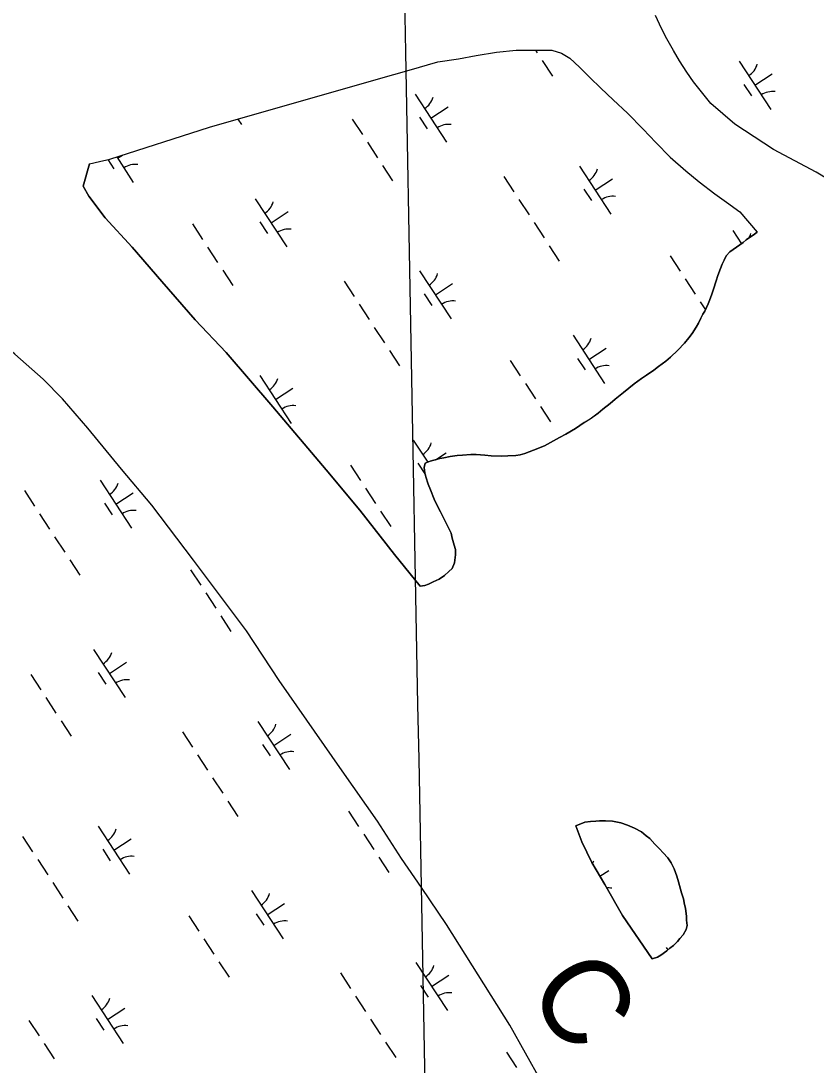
# Model space of a CAD drawing. Extents: x 3945642 to 3966284, y 206476 to 228921.
# Drawn here: x 3961973 to 3962666, y 215429 to 216338 of the extents above; entities that cross this region are included whole.
import ezdxf

# ---------------------------------------------------------------- set-up
doc = ezdxf.new("R2010")
doc.units = 0
for name, color, linetype in [('V-GRID-MAJR', 7, 'Continuous'), ('V-RIVR-IDEN', 7, 'Continuous'), ('V-TOPO-SHOR', 7, 'Continuous'), ('V-WETL-SWMP', 7, 'Continuous')]:
    doc.layers.add(name, color=color, linetype=linetype)

msp = doc.modelspace()

# ---------------------------------------------------------------- linework, layer by layer
at = {"layer": 'V-GRID-MAJR'}
msp.add_spline([(3962398.82, 211465.27), (3962380.88, 212428.56), (3962268.05, 218488.48), (3962267.27, 218530.32)], degree=3, dxfattribs=at)
at = {"layer": 'V-TOPO-SHOR'}
for points in [[(3962665.82, 216206.13), (3962628.66, 216225.93), (3962595.09, 216247.97), (3962574.2, 216266.08), (3962558.97, 216285), (3962553.28, 216293.31), (3962546.93, 216303.24), (3962541.71, 216312.12), (3962535.84, 216322.41), (3962531.09, 216331.29), (3962525.89, 216342.71)], [(3962033.13, 216213.59), (3962041.94, 216215.43), (3962050.86, 216217.6), (3962137.79, 216245.49), (3962284.94, 216287.61), (3962311.6, 216294.91), (3962336.59, 216302.33), (3962354.54, 216304.9), (3962369.81, 216307.71), (3962387.65, 216310.61), (3962404.81, 216312.51), (3962435.77, 216312.44), (3962444.22, 216309.72), (3962451.33, 216305.44), (3962459.85, 216297.59), (3962468.82, 216288.63), (3962478.34, 216279.33), (3962488.98, 216269.13), (3962501.71, 216257.47), (3962515.22, 216243.58), (3962526.18, 216232.16), (3962538.69, 216219.39), (3962552.43, 216207.28), (3962563.95, 216197.74), (3962577.59, 216187.3), (3962587.79, 216180.23), (3962599.44, 216171.8), (3962614.54, 216154.01)], [(3962033.13, 216213.59), (3962027.54, 216193.99), (3962032.54, 216185.36), (3962046.9, 216166.42), (3962070.25, 216140.88), (3962096.16, 216110.95), (3962125.32, 216077.58), (3962152.2, 216049.15), (3962192.76, 216002.06), (3962239.29, 215947.29), (3962268.58, 215912.15), (3962298.81, 215873.32), (3962321.04, 215845.87)], [(3962596.53, 215120.17), (3962538.23, 215226.12), (3962486.2, 215320.53), (3962426.39, 215415), (3962399.23, 215463.78), (3962344.02, 215551.39), (3962322.36, 215583.48), (3962304.75, 215608.71), (3962284.05, 215641.21), (3962253.16, 215685.1), (3962198.45, 215763.69), (3962169.75, 215807.02), (3962123.81, 215868.62), (3962087.49, 215916.5), (3962061.18, 215947.8), (3962031.61, 215983.49), (3962009.78, 216008.89), (3961992.8, 216026.2), (3961968.21, 216047.92), (3961939.27, 216072.68), (3961907.85, 216096.08), (3961870.85, 216121.16), (3961828.9, 216140.94), (3961793.45, 216157.39)], [(3962321.04, 215845.87), (3962325.15, 215846.53), (3962328.34, 215847.65), (3962332.45, 215849.67), (3962337.7, 215851.92), (3962342.27, 215855.08), (3962346.17, 215858.7), (3962348.91, 215861.41), (3962350.99, 215866.18), (3962351.94, 215873.23), (3962351.75, 215877.79), (3962350.63, 215881.44), (3962349.07, 215887.6), (3962347.96, 215891.93), (3962344.81, 215898.55), (3962342.33, 215903.58), (3962338.73, 215910.65), (3962336.03, 215916.13), (3962333.33, 215921.62), (3962329.96, 215929.61), (3962328.17, 215934.62), (3962326.16, 215941.01), (3962325.27, 215944.66), (3962324.62, 215949.22), (3962325.32, 215953.08), (3962329.66, 215954.65), (3962333.08, 215955.54), (3962338.32, 215956.88), (3962341.74, 215957.54), (3962347.21, 215958.65), (3962353.37, 215959.52), (3962357.92, 215959.95), (3962365.21, 215960.36), (3962369.77, 215960.56), (3962377.5, 215959.83), (3962382.96, 215959.34), (3962391.85, 215959.06), (3962397.31, 215959.26), (3962404.37, 215959.67), (3962408.25, 215960.33), (3962412.12, 215961.45), (3962419.88, 215964.13), (3962429.24, 215968.18), (3962434.49, 215970.88), (3962442.48, 215975.16), (3962447.97, 215978.31), (3962456.2, 215983.27), (3962463.97, 215988.46), (3962469, 215991.4), (3962476.08, 215996.59), (3962480.2, 215999.98), (3962486.38, 216004.95), (3962490.95, 216008.57), (3962498.05, 216014.45), (3962502.85, 216018.29), (3962507.43, 216022.13), (3962513.83, 216026.65), (3962518.17, 216029.58), (3962524.58, 216033.87), (3962528.69, 216037.03), (3962535.1, 216041.78), (3962538.98, 216045.17), (3962545.4, 216051.28), (3962551.13, 216057.39), (3962555.02, 216062.15), (3962557.78, 216065.78), (3962561.46, 216071.45), (3962563.3, 216074.85), (3962565.37, 216079.17), (3962567.21, 216082.57), (3962568.82, 216085.29), (3962571.82, 216091.65), (3962572.98, 216094.6), (3962575.06, 216100.06), (3962576.45, 216104.38), (3962578.77, 216111.65), (3962580.16, 216116.19), (3962582.48, 216122.33), (3962584.09, 216126.19), (3962585.71, 216129.59), (3962587.55, 216133.45), (3962590.76, 216136.85), (3962602.19, 216144.98), (3962604.94, 216147.24), (3962607.91, 216149.27), (3962610.88, 216151.53), (3962614.54, 216154.01)], [(3962523.04, 215521.51), (3962527.84, 215523.07), (3962530.58, 215524.65), (3962535.83, 215528.49), (3962538.35, 215530.75), (3962541.56, 215533.01), (3962544.99, 215536.63), (3962547.06, 215539.12), (3962550.04, 215542.52), (3962552.57, 215547.06), (3962553.5, 215550.47), (3962553.07, 215555.03), (3962552.86, 215558.44), (3962552.22, 215565.73), (3962551.33, 215568.7), (3962550.22, 215573.71), (3962548.66, 215578.96), (3962546.87, 215585.34), (3962545.98, 215588.54), (3962544.42, 215593.33), (3962542.18, 215599.94), (3962539.48, 215604.97), (3962536.77, 215609.31), (3962532.7, 215613.89), (3962529.53, 215617.33), (3962525.46, 215621.45), (3962520.93, 215626.26), (3962517.99, 215628.55), (3962513.68, 215631.99), (3962507.55, 215635.21), (3962501.65, 215637.98), (3962495.74, 215639.84), (3962488.46, 215641.48), (3962482.32, 215641.51), (3962477.31, 215641.54), (3962473.89, 215641.33), (3962469.33, 215640.91), (3962464.32, 215640.48), (3962456.53, 215637.32)], [(3962456.53, 215637.32), (3962461.91, 215623.22), (3962470.54, 215605.27), (3962481.77, 215586.08), (3962497.18, 215559.36), (3962523.04, 215521.51)]]:
    msp.add_lwpolyline(points, dxfattribs=at)
at = {"layer": 'V-WETL-SWMP'}
for p, q in [((3962531.1, 216331.29), (3962525.89, 216342.71)), ((3962535.84, 216322.41), (3962531.1, 216331.29)), ((3962541.71, 216312.12), (3962535.84, 216322.41)), ((3962421.43, 216312.47), (3962423.04, 216310)), ((3962546.93, 216303.24), (3962541.71, 216312.12)), ((3962427.43, 216303.31), (3962436.2, 216289.93)), ((3962553.28, 216293.31), (3962546.93, 216303.24)), ((3962598.89, 216302.76), (3962626.29, 216260.93)), ((3962558.97, 216285), (3962553.28, 216293.31)), ((3962612.59, 216281.85), (3962627.65, 216291.71)), ((3962574.2, 216266.08), (3962558.97, 216285)), ((3962602.85, 216282.64), (3962609.42, 216272.6)), ((3962316.68, 216274.15), (3962344.08, 216232.32)), ((3962595.09, 216247.97), (3962574.2, 216266.08)), ((3962330.38, 216253.24), (3962345.44, 216263.1)), ((3962162.33, 216252.51), (3962165.52, 216247.64)), ((3962261.99, 216252.31), (3962270.75, 216238.93)), ((3962320.64, 216254.03), (3962327.21, 216243.99)), ((3962628.66, 216225.93), (3962595.09, 216247.97)), ((3962275.14, 216232.23), (3962283.91, 216218.85)), ((3962056.86, 216219.53), (3962071.35, 216197.4)), ((3962057.65, 216218.31), (3962062.06, 216221.19)), ((3962665.82, 216206.13), (3962628.66, 216225.93)), ((3962049.16, 216217.19), (3962054.49, 216209.06)), ((3962288.29, 216212.16), (3962297.06, 216198.78)), ((3962459.75, 216211.61), (3962487.15, 216169.78)), ((3962393.96, 216202.48), (3962402.73, 216189.1)), ((3962473.45, 216190.69), (3962488.51, 216200.56)), ((3962715.54, 216176.43), (3962665.82, 216206.13)), ((3962463.71, 216191.49), (3962470.29, 216181.45)), ((3962177.54, 216183), (3962204.94, 216141.17)), ((3962407.11, 216182.41), (3962415.88, 216169.02)), ((3962191.24, 216162.08), (3962206.3, 216171.95)), ((3962122.85, 216161.16), (3962131.62, 216147.78)), ((3962181.5, 216162.88), (3962188.07, 216152.84)), ((3962420.26, 216162.33), (3962429.03, 216148.95)), ((3962593.34, 216155.38), (3962600.8, 216143.99)), ((3962136, 216141.08), (3962144.77, 216127.7)), ((3962433.41, 216142.26), (3962442.18, 216128.87)), ((3962538.65, 216133.54), (3962547.41, 216120.16)), ((3962149.15, 216121.01), (3962157.92, 216107.62)), ((3962320.61, 216120.45), (3962348.01, 216078.63)), ((3962254.82, 216111.33), (3962263.59, 216097.95)), ((3962334.31, 216099.54), (3962349.37, 216109.41)), ((3962551.8, 216113.47), (3962560.57, 216100.08)), ((3962324.57, 216100.33), (3962331.15, 216090.3)), ((3962267.97, 216091.25), (3962276.74, 216077.87)), ((3962564.95, 216093.39), (3962569.42, 216086.56)), ((3962281.12, 216071.18), (3962289.89, 216057.8)), ((3962454.2, 216064.23), (3962481.6, 216022.4)), ((3961992.8, 216026.2), (3961968.21, 216047.92)), ((3962294.28, 216051.1), (3962303.04, 216037.72)), ((3962467.9, 216043.32), (3962482.96, 216053.18)), ((3962399.51, 216042.39), (3962408.27, 216029.01)), ((3962458.16, 216044.11), (3962464.73, 216034.07)), ((3962181.47, 216029.3), (3962208.87, 215987.48)), ((3962009.77, 216008.88), (3961992.8, 216026.2)), ((3962412.66, 216022.32), (3962421.43, 216008.93)), ((3962195.17, 216008.39), (3962210.23, 216018.26)), ((3962031.61, 215983.49), (3962009.77, 216008.88)), ((3962425.81, 216002.24), (3962434.58, 215988.86)), ((3962061.18, 215947.8), (3962031.61, 215983.49)), ((3962315.06, 215973.08), (3962327.62, 215953.91)), ((3962334.45, 215955.89), (3962343.82, 215962.03)), ((3962087.49, 215916.5), (3962061.18, 215947.8)), ((3962260.37, 215951.24), (3962269.14, 215937.86)), ((3962319.02, 215952.96), (3962325.59, 215942.92)), ((3962042.34, 215938.15), (3962069.74, 215896.33)), ((3961976.54, 215929.03), (3961985.31, 215915.64)), ((3962273.52, 215931.16), (3962282.29, 215917.78)), ((3962056.04, 215917.24), (3962071.09, 215927.1)), ((3962046.29, 215918.03), (3962052.87, 215907.99)), ((3962123.81, 215868.62), (3962087.49, 215916.5)), ((3962286.67, 215911.09), (3962295.44, 215897.7)), ((3961989.69, 215908.95), (3961998.46, 215895.57)), ((3962002.85, 215888.88), (3962011.61, 215875.49)), ((3962016, 215868.8), (3962024.77, 215855.42)), ((3962169.75, 215807.02), (3962123.81, 215868.62)), ((3962121.23, 215860.09), (3962130, 215846.7)), ((3962134.38, 215840.01), (3962143.15, 215826.63)), ((3962147.53, 215819.94), (3962156.3, 215806.55)), ((3962198.45, 215763.69), (3962169.75, 215807.02)), ((3962036.78, 215790.77), (3962064.18, 215748.95)), ((3962050.48, 215769.86), (3962065.54, 215779.73)), ((3961982.09, 215768.94), (3961990.86, 215755.55)), ((3962040.74, 215770.65), (3962047.32, 215760.62)), ((3962253.16, 215685.1), (3962198.45, 215763.69)), ((3961995.24, 215748.86), (3962004.01, 215735.48)), ((3962008.39, 215728.79), (3962017.16, 215715.4)), ((3962179.86, 215728.23), (3962207.26, 215686.41)), ((3962114.06, 215719.11), (3962122.83, 215705.72)), ((3962193.56, 215707.32), (3962208.61, 215717.18)), ((3962183.81, 215708.11), (3962190.39, 215698.07)), ((3962127.21, 215699.03), (3962135.98, 215685.65)), ((3962284.04, 215641.21), (3962253.16, 215685.1)), ((3962140.37, 215678.96), (3962149.13, 215665.57)), ((3962153.52, 215658.88), (3962162.29, 215645.5)), ((3962258.75, 215650.17), (3962267.52, 215636.79)), ((3962040.72, 215637.08), (3962068.12, 215595.26)), ((3962304.75, 215608.71), (3962284.04, 215641.21)), ((3961974.92, 215627.96), (3961983.69, 215614.57)), ((3962271.9, 215630.09), (3962280.67, 215616.71)), ((3962054.42, 215616.17), (3962069.47, 215626.03)), ((3962044.68, 215616.96), (3962051.25, 215606.92)), ((3962285.05, 215610.02), (3962293.82, 215596.63)), ((3961988.08, 215607.88), (3961996.84, 215594.5)), ((3962322.36, 215583.48), (3962304.75, 215608.71)), ((3962477.52, 215593.34), (3962485.27, 215598.42)), ((3962001.23, 215587.81), (3962010, 215574.42)), ((3962344.02, 215551.39), (3962322.36, 215583.48)), ((3962174.3, 215580.86), (3962201.7, 215539.03)), ((3962014.38, 215567.73), (3962023.15, 215554.35)), ((3962188, 215559.94), (3962203.06, 215569.81)), ((3962119.61, 215559.02), (3962128.38, 215545.63)), ((3962178.26, 215560.73), (3962184.84, 215550.7)), ((3962399.23, 215463.78), (3962344.02, 215551.39)), ((3962132.76, 215538.94), (3962141.53, 215525.56)), ((3962535.41, 215531.4), (3962536.77, 215529.33)), ((3962145.91, 215518.87), (3962154.68, 215505.48)), ((3962317.38, 215518.31), (3962344.78, 215476.49)), ((3962251.58, 215509.19), (3962260.35, 215495.81)), ((3962331.08, 215497.4), (3962346.13, 215507.27)), ((3962321.33, 215498.19), (3962327.91, 215488.15)), ((3962035.16, 215489.7), (3962062.56, 215447.88)), ((3962264.74, 215489.11), (3962273.5, 215475.73)), ((3962048.86, 215468.79), (3962063.92, 215478.66)), ((3961980.47, 215467.87), (3961989.24, 215454.48)), ((3962039.12, 215469.58), (3962045.7, 215459.55)), ((3962277.89, 215469.04), (3962286.65, 215455.65)), ((3962426.39, 215414.99), (3962399.23, 215463.78)), ((3961993.62, 215447.79), (3962002.39, 215434.41)), ((3962291.04, 215448.96), (3962299.81, 215435.58)), ((3962396.27, 215440.25), (3962405.04, 215426.87))]:
    msp.add_line(p, q, dxfattribs=at)
for points in [[(3962033.13, 216213.59), (3962041.94, 216215.43), (3962050.86, 216217.6), (3962137.79, 216245.49), (3962284.94, 216287.61), (3962311.6, 216294.91), (3962336.59, 216302.33), (3962354.54, 216304.9), (3962369.81, 216307.71), (3962387.65, 216310.61), (3962404.81, 216312.51), (3962435.77, 216312.44), (3962444.22, 216309.71), (3962451.32, 216305.44), (3962459.85, 216297.59), (3962468.82, 216288.63), (3962478.34, 216279.33), (3962488.98, 216269.13), (3962501.71, 216257.47), (3962515.22, 216243.58), (3962526.18, 216232.16), (3962538.69, 216219.39), (3962552.43, 216207.28), (3962563.95, 216197.74), (3962577.59, 216187.3), (3962587.79, 216180.23), (3962599.44, 216171.8), (3962614.54, 216154.01), (3962610.88, 216151.53), (3962607.91, 216149.27), (3962604.94, 216147.24), (3962602.19, 216144.98), (3962590.76, 216136.85), (3962587.55, 216133.45), (3962585.71, 216129.59), (3962584.09, 216126.19), (3962582.48, 216122.33), (3962580.16, 216116.19), (3962578.77, 216111.65), (3962576.45, 216104.37), (3962575.06, 216100.06), (3962572.98, 216094.6), (3962571.82, 216091.65), (3962568.82, 216085.29), (3962567.21, 216082.57), (3962565.37, 216079.17), (3962563.3, 216074.85), (3962561.46, 216071.45), (3962557.78, 216065.78), (3962555.02, 216062.15), (3962551.13, 216057.39), (3962545.4, 216051.28), (3962538.99, 216045.17), (3962535.1, 216041.78), (3962528.69, 216037.03), (3962524.58, 216033.87), (3962518.17, 216029.58), (3962513.83, 216026.65), (3962507.43, 216022.13), (3962502.85, 216018.29), (3962498.05, 216014.45), (3962490.95, 216008.57), (3962486.38, 216004.95), (3962480.2, 215999.98), (3962476.08, 215996.59), (3962468.99, 215991.39), (3962463.97, 215988.46), (3962456.2, 215983.27), (3962447.97, 215978.31), (3962442.49, 215975.16), (3962434.49, 215970.88), (3962429.24, 215968.18), (3962419.88, 215964.14), (3962412.12, 215961.45), (3962408.25, 215960.33), (3962404.37, 215959.67), (3962397.31, 215959.26), (3962391.84, 215959.06), (3962382.96, 215959.34), (3962377.5, 215959.83), (3962369.77, 215960.56), (3962365.21, 215960.36), (3962357.92, 215959.95), (3962353.37, 215959.52), (3962347.21, 215958.65), (3962341.74, 215957.54), (3962338.32, 215956.88), (3962333.08, 215955.54), (3962329.66, 215954.65), (3962325.32, 215953.08), (3962324.62, 215949.22), (3962325.27, 215944.66), (3962326.16, 215941.01), (3962328.17, 215934.62), (3962329.96, 215929.6), (3962333.33, 215921.61), (3962336.03, 215916.13), (3962338.73, 215910.65), (3962342.33, 215903.57), (3962344.81, 215898.55), (3962347.96, 215891.93)], [(3962347.96, 215891.93), (3962349.07, 215887.6), (3962350.63, 215881.44), (3962351.74, 215877.79), (3962351.94, 215873.23), (3962350.99, 215866.18), (3962348.91, 215861.41), (3962346.17, 215858.7), (3962342.27, 215855.08), (3962337.7, 215851.92), (3962332.45, 215849.67), (3962328.34, 215847.65), (3962325.15, 215846.53), (3962321.04, 215845.87), (3962298.81, 215873.32), (3962268.58, 215912.15), (3962239.28, 215947.29), (3962192.76, 216002.06), (3962152.2, 216049.15), (3962125.32, 216077.58), (3962096.16, 216110.95), (3962070.25, 216140.88), (3962046.9, 216166.42), (3962032.54, 216185.36), (3962027.54, 216193.99), (3962033.13, 216213.59)]]:
    msp.add_lwpolyline(points, dxfattribs=at)
msp.add_lwpolyline([(3962523.04, 215521.51), (3962497.18, 215559.36), (3962481.77, 215586.08), (3962470.54, 215605.27), (3962461.91, 215623.21), (3962456.53, 215637.32), (3962464.32, 215640.48), (3962469.33, 215640.91), (3962473.89, 215641.33), (3962477.31, 215641.54), (3962482.32, 215641.51), (3962488.46, 215641.48), (3962495.74, 215639.84), (3962501.65, 215637.98), (3962507.55, 215635.21), (3962513.68, 215631.99), (3962517.99, 215628.55), (3962520.93, 215626.26), (3962525.46, 215621.45), (3962529.53, 215617.33), (3962532.7, 215613.89), (3962536.77, 215609.31), (3962539.48, 215604.97), (3962542.18, 215599.95), (3962544.42, 215593.33), (3962545.98, 215588.54), (3962546.88, 215585.35), (3962548.66, 215578.96), (3962550.22, 215573.71), (3962551.33, 215568.7), (3962552.22, 215565.73), (3962552.86, 215558.44), (3962553.07, 215555.03), (3962553.5, 215550.47), (3962552.57, 215547.06), (3962550.04, 215542.52), (3962547.06, 215539.12), (3962544.99, 215536.63), (3962541.56, 215533.01), (3962538.35, 215530.75), (3962535.84, 215528.49), (3962530.58, 215524.65), (3962527.83, 215523.07)], close=True, dxfattribs=at)
for centre, start, end in [((3962597.65, 216305.08), 302.45745, 344.00111), ((3962627.93, 216258.87), 82.45745, 124.00111), ((3962315.44, 216276.47), 302.45745, 344.00111), ((3962345.71, 216230.26), 82.45745, 124.00111), ((3962072.99, 216195.34), 82.45745, 124.00111), ((3962458.51, 216213.93), 302.45745, 344.00111), ((3962488.79, 216167.72), 82.45745, 124.00111), ((3962176.3, 216185.32), 302.45745, 344.00111), ((3962206.57, 216139.11), 82.45745, 124.00111), ((3962592.1, 216157.7), 330.0241, 344.00111), ((3962319.38, 216122.78), 302.45745, 344.00111), ((3962349.65, 216076.57), 82.45745, 124.00111), ((3962452.96, 216066.55), 302.45745, 344.00111), ((3962483.23, 216020.34), 82.45745, 124.00111), ((3962180.24, 216031.63), 302.45745, 344.00111), ((3962210.51, 215985.42), 82.45745, 124.00111), ((3962313.82, 215975.4), 302.45745, 344.00111), ((3962041.1, 215940.48), 302.45745, 344.00111), ((3962071.37, 215894.27), 82.45745, 124.00111), ((3962035.55, 215793.1), 302.45745, 344.00111), ((3962065.82, 215746.89), 82.45745, 124.00111), ((3962178.62, 215730.56), 302.45745, 344.00111), ((3962208.89, 215684.35), 82.45745, 124.00111), ((3962039.48, 215639.4), 302.45745, 344.00111), ((3962069.75, 215593.19), 82.45745, 124.00111), ((3962455.28, 215611.79), 334.45444, 344.00111), ((3962485.55, 215565.58), 82.45745, 96.6852), ((3962173.07, 215583.18), 302.45745, 344.00111), ((3962203.34, 215536.97), 82.45745, 124.00111), ((3962316.14, 215520.64), 302.45745, 344.00111), ((3962346.41, 215474.43), 82.45745, 124.00111), ((3962033.93, 215492.03), 302.45745, 344.00111), ((3962064.2, 215445.82), 82.45745, 124.00111)]:
    msp.add_arc(centre, 17.62, start, end, dxfattribs=at)

# ---------------------------------------------------------------- texts
at = {"layer": 'V-RIVR-IDEN'}
msp.add_text('C', height=75, rotation=303.9191, dxfattribs=at).set_placement((3962412.79, 215494.92))

doc.saveas('drawing.dxf')
